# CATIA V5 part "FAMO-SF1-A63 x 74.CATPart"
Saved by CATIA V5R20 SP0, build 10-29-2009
Part number: FAMO-SF1-A63 x 74
Definition: NONE
Nomenclature: FAMO-SF1-A63 x 74
Source: Unknown
Description: FAMO-SF1-A63 x 74
Bounding box of the stored display mesh (mm): x -13 to 61, y -46 to 46, z -46 to 46
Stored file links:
  C:\Users\Utente\Desktop\IO LAVORO\3D X SITO CF\X SITO\FAMO\FAMO-SF1-A63 x 74.CATPart
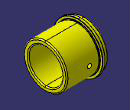
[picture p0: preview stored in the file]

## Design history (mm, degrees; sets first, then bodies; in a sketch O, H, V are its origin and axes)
Body1 "FAMO-SF1-A63 x 74" (main body)
  Solid1: solid without history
